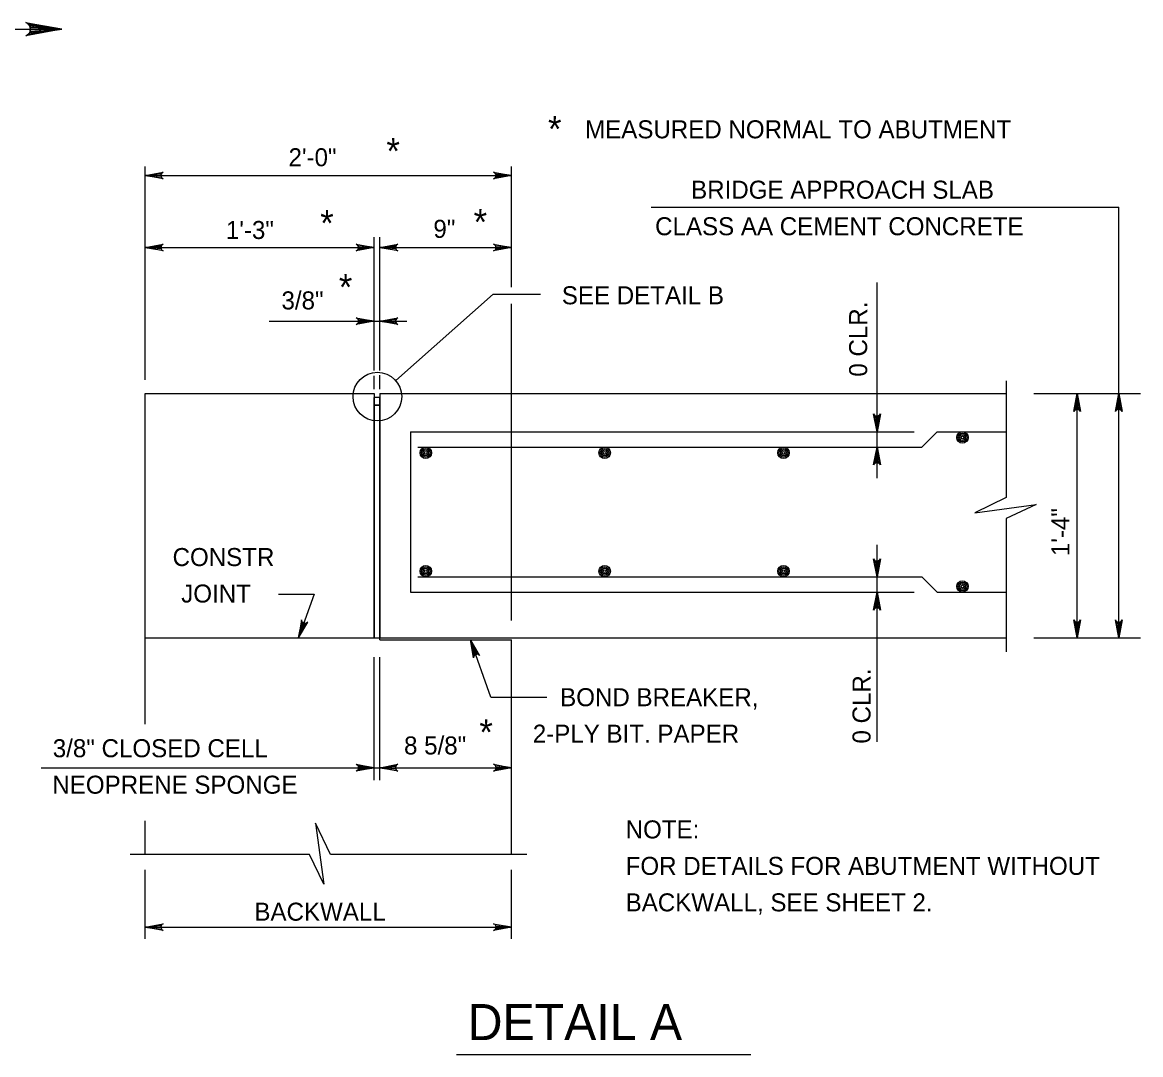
# Model space of a CAD drawing. Extents: x 638079 to 640019, y 297691 to 298879.
# Drawn here: x 638757.3 to 638943.4, y 298459.3 to 298631 of the extents above; entities that cross this region are included whole.
import ezdxf

# ---------------------------------------------------------------- set-up
doc = ezdxf.new("R2010")
doc.units = 0
doc.layers.add('1', color=7, linetype='Continuous')

msp = doc.modelspace()

# ---------------------------------------------------------------- linework, layer by layer
at = {"layer": '1'}
for p, q in [((638683.38, 298629.92), (638763.86, 298629.92)), ((638777.75, 298571.56), (638777.75, 298607.05)), ((638838.71, 298586.96), (638838.71, 298607.05)), ((638777.75, 298605.56), (638838.71, 298605.56)), ((638861.93, 298600.3), (638939.71, 298600.3)), ((638939.71, 298528.61), (638939.71, 298600.3)), ((638815.85, 298573.11), (638815.85, 298595.29)), ((638816.8, 298583.27), (638816.8, 298595.29)), ((638777.75, 298593.55), (638815.85, 298593.55)), ((638816.8, 298593.55), (638838.71, 298593.55)), ((638899.5, 298555.2), (638899.5, 298587.76)), ((638835.66, 298585.8), (638819.42, 298571.45)), ((638835.66, 298585.8), (638843.52, 298585.8)), ((638816.8, 298573.11), (638816.8, 298583.27)), ((638838.71, 298531.48), (638838.71, 298584.18)), ((638798.37, 298581.31), (638821.29, 298581.31)), ((638815.85, 298570.01), (638815.85, 298572.2)), ((638816.8, 298570.01), (638816.8, 298572.32)), ((638920.99, 298571.37), (638920.99, 298551.97)), ((638777.75, 298569.25), (638815.85, 298569.25)), ((638777.75, 298514.24), (638777.75, 298569.25)), ((638815.85, 298569.25), (638815.85, 298528.61)), ((638815.85, 298528.61), (638815.85, 298568.61)), ((638816.8, 298569.25), (638920.99, 298569.25)), ((638816.8, 298569.25), (638816.8, 298528.61)), ((638925.57, 298569.25), (638943.36, 298569.25)), ((638932.79, 298528.61), (638932.79, 298569.25)), ((638815.85, 298567.34), (638816.8, 298567.34)), ((638821.88, 298562.9), (638821.88, 298536.23)), ((638821.88, 298562.9), (638905.7, 298562.9)), ((638906.97, 298560.36), (638909.51, 298562.9)), ((638909.51, 298562.9), (638920.99, 298562.9)), ((638823.1, 298560.36), (638906.97, 298560.36)), ((638920.99, 298548.45), (638920.99, 298526.3)), ((638899.5, 298511.32), (638899.5, 298544.07)), ((638823.1, 298538.77), (638906.97, 298538.77)), ((638906.97, 298538.77), (638909.51, 298536.23)), ((638821.88, 298536.23), (638905.7, 298536.23)), ((638909.51, 298536.23), (638920.99, 298536.23)), ((638799.91, 298535.9), (638805.86, 298535.9)), ((638805.86, 298535.9), (638803.26, 298528.61)), ((638777.75, 298528.61), (638815.85, 298528.61)), ((638815.85, 298528.61), (638920.99, 298528.61)), ((638815.85, 298528.61), (638838.71, 298528.61)), ((638816.8, 298528.3), (638816.8, 298528.61)), ((638816.8, 298528.3), (638838.71, 298528.3)), ((638835.26, 298518.76), (638831.86, 298528.3)), ((638838.71, 298492.58), (638838.71, 298528.3)), ((638925.57, 298528.61), (638943.36, 298528.61)), ((638815.85, 298504.91), (638815.85, 298525.41)), ((638816.8, 298504.91), (638816.8, 298525.41)), ((638835.26, 298518.76), (638844.55, 298518.76)), ((638760.45, 298507.01), (638838.71, 298507.01)), ((638777.75, 298492.58), (638777.75, 298498.18)), ((638805.08, 298492.58), (638775.22, 298492.58)), ((638841.26, 298492.58), (638808.6, 298492.58)), ((638777.75, 298478.53), (638777.75, 298490.03)), ((638838.71, 298478.53), (638838.71, 298490.03)), ((638777.75, 298480.49), (638838.71, 298480.49)), ((638829.54, 298459.26), (638878.48, 298459.26))]:
    msp.add_line(p, q, dxfattribs=at)
for points in [[(638763.86, 298629.92), (638757.89, 298628.8), (638758.12, 298628.96), (638758.35, 298629.12), (638758.47, 298629.32), (638758.59, 298629.52), (638758.63, 298629.72), (638758.66, 298629.92), (638758.63, 298630.12), (638758.59, 298630.32), (638758.47, 298630.52), (638758.35, 298630.72), (638758.12, 298630.88), (638757.89, 298631.04), (638763.86, 298629.92), (638758.12, 298630.88), (638758.35, 298630.72), (638763.86, 298629.92), (638758.47, 298630.52), (638758.59, 298630.32), (638763.86, 298629.92), (638758.63, 298630.12), (638758.66, 298629.92), (638763.86, 298629.92), (638758.63, 298629.72), (638758.59, 298629.52), (638763.86, 298629.92), (638758.47, 298629.32), (638758.35, 298629.12), (638763.86, 298629.92), (638758.12, 298628.96)], [(638777.75, 298605.56), (638780.73, 298606.12), (638780.5, 298605.96), (638780.38, 298605.76), (638780.35, 298605.56), (638780.38, 298605.36), (638780.5, 298605.16), (638780.73, 298605), (638777.75, 298605.56), (638780.5, 298605.16), (638780.38, 298605.36), (638777.75, 298605.56), (638780.35, 298605.56), (638780.38, 298605.76), (638777.75, 298605.56), (638780.5, 298605.96)], [(638838.71, 298605.56), (638835.72, 298605), (638835.95, 298605.16), (638836.07, 298605.36), (638836.11, 298605.56), (638836.07, 298605.76), (638835.95, 298605.96), (638835.72, 298606.12), (638838.71, 298605.56), (638835.95, 298605.96), (638836.07, 298605.76), (638838.71, 298605.56), (638836.11, 298605.56), (638836.07, 298605.36), (638838.71, 298605.56), (638835.95, 298605.16)], [(638777.75, 298593.55), (638780.73, 298594.11), (638780.5, 298593.95), (638780.38, 298593.75), (638780.35, 298593.55), (638780.38, 298593.35), (638780.5, 298593.15), (638780.73, 298592.99), (638777.75, 298593.55), (638780.5, 298593.15), (638780.38, 298593.35), (638777.75, 298593.55), (638780.35, 298593.55), (638780.38, 298593.75), (638777.75, 298593.55), (638780.5, 298593.95)], [(638815.85, 298593.55), (638812.86, 298592.99), (638813.09, 298593.15), (638813.21, 298593.35), (638813.25, 298593.55), (638813.21, 298593.75), (638813.09, 298593.95), (638812.86, 298594.11), (638815.85, 298593.55), (638813.09, 298593.95), (638813.21, 298593.75), (638815.85, 298593.55), (638813.25, 298593.55), (638813.21, 298593.35), (638815.85, 298593.55), (638813.09, 298593.15)], [(638816.8, 298593.55), (638819.78, 298594.11), (638819.55, 298593.95), (638819.43, 298593.75), (638819.4, 298593.55), (638819.43, 298593.35), (638819.55, 298593.15), (638819.78, 298592.99), (638816.8, 298593.55), (638819.55, 298593.15), (638819.43, 298593.35), (638816.8, 298593.55), (638819.4, 298593.55), (638819.43, 298593.75), (638816.8, 298593.55), (638819.55, 298593.95)], [(638838.71, 298593.55), (638835.72, 298592.99), (638835.95, 298593.15), (638836.07, 298593.35), (638836.11, 298593.55), (638836.07, 298593.75), (638835.95, 298593.95), (638835.72, 298594.11), (638838.71, 298593.55), (638835.95, 298593.95), (638836.07, 298593.75), (638838.71, 298593.55), (638836.11, 298593.55), (638836.07, 298593.35), (638838.71, 298593.55), (638835.95, 298593.15)], [(638815.85, 298581.31), (638812.86, 298580.75), (638813.09, 298580.91), (638813.21, 298581.11), (638813.25, 298581.31), (638813.21, 298581.51), (638813.09, 298581.71), (638812.86, 298581.87), (638815.85, 298581.31), (638813.09, 298581.71), (638813.21, 298581.51), (638815.85, 298581.31), (638813.25, 298581.31), (638813.21, 298581.11), (638815.85, 298581.31), (638813.09, 298580.91)], [(638816.8, 298581.31), (638819.78, 298581.87), (638819.55, 298581.71), (638819.43, 298581.51), (638819.4, 298581.31), (638819.43, 298581.11), (638819.55, 298580.91), (638819.78, 298580.75), (638816.8, 298581.31), (638819.55, 298580.91), (638819.43, 298581.11), (638816.8, 298581.31), (638819.4, 298581.31), (638819.43, 298581.51), (638816.8, 298581.31), (638819.55, 298581.71)], [(638932.79, 298569.25), (638933.34, 298566.27), (638933.19, 298566.5), (638932.99, 298566.61), (638932.79, 298566.65), (638932.59, 298566.61), (638932.39, 298566.5), (638932.23, 298566.27), (638932.79, 298569.25), (638932.39, 298566.5), (638932.59, 298566.61), (638932.79, 298569.25), (638932.79, 298566.65), (638932.99, 298566.61), (638932.79, 298569.25), (638933.19, 298566.5)], [(638939.71, 298569.25), (638940.27, 298566.27), (638940.11, 298566.5), (638939.91, 298566.61), (638939.71, 298566.65), (638939.51, 298566.61), (638939.31, 298566.5), (638939.15, 298566.27), (638939.71, 298569.25), (638939.31, 298566.5), (638939.51, 298566.61), (638939.71, 298569.25), (638939.71, 298566.65), (638939.91, 298566.61), (638939.71, 298569.25), (638940.11, 298566.5)], [(638899.5, 298562.9), (638898.94, 298565.88), (638899.1, 298565.65), (638899.3, 298565.53), (638899.5, 298565.5), (638899.7, 298565.53), (638899.9, 298565.65), (638900.06, 298565.88), (638899.5, 298562.9), (638899.9, 298565.65), (638899.7, 298565.53), (638899.5, 298562.9), (638899.5, 298565.5), (638899.3, 298565.53), (638899.5, 298562.9), (638899.1, 298565.65)], [(638899.5, 298560.36), (638900.06, 298557.38), (638899.9, 298557.61), (638899.7, 298557.73), (638899.5, 298557.76), (638899.3, 298557.73), (638899.1, 298557.61), (638898.94, 298557.38), (638899.5, 298560.36), (638899.1, 298557.61), (638899.3, 298557.73), (638899.5, 298560.36), (638899.5, 298557.76), (638899.7, 298557.73), (638899.5, 298560.36), (638899.9, 298557.61)], [(638920.99, 298551.97), (638915.8, 298549.43), (638925.95, 298550.81), (638920.99, 298548.45)], [(638899.5, 298538.77), (638898.94, 298541.75), (638899.1, 298541.52), (638899.3, 298541.4), (638899.5, 298541.37), (638899.7, 298541.4), (638899.9, 298541.52), (638900.06, 298541.75), (638899.5, 298538.77), (638899.9, 298541.52), (638899.7, 298541.4), (638899.5, 298538.77), (638899.5, 298541.37), (638899.3, 298541.4), (638899.5, 298538.77), (638899.1, 298541.52)], [(638899.5, 298536.23), (638900.06, 298533.25), (638899.9, 298533.48), (638899.7, 298533.6), (638899.5, 298533.63), (638899.3, 298533.6), (638899.1, 298533.48), (638898.94, 298533.25), (638899.5, 298536.23), (638899.1, 298533.48), (638899.3, 298533.6), (638899.5, 298536.23), (638899.5, 298533.63), (638899.7, 298533.6), (638899.5, 298536.23), (638899.9, 298533.48)], [(638803.26, 298528.61), (638804.79, 298531.23), (638804.56, 298531.07), (638804.33, 298531.02), (638804.13, 298531.06), (638803.95, 298531.16), (638803.81, 298531.34), (638803.73, 298531.61), (638803.26, 298528.61), (638803.81, 298531.34), (638803.95, 298531.16), (638803.26, 298528.61), (638804.13, 298531.06), (638804.33, 298531.02), (638803.26, 298528.61), (638804.56, 298531.07)], [(638932.79, 298528.61), (638932.23, 298531.59), (638932.39, 298531.36), (638932.59, 298531.24), (638932.79, 298531.21), (638932.99, 298531.24), (638933.19, 298531.36), (638933.34, 298531.59), (638932.79, 298528.61), (638933.19, 298531.36), (638932.99, 298531.24), (638932.79, 298528.61), (638932.79, 298531.21), (638932.59, 298531.24), (638932.79, 298528.61), (638932.39, 298531.36)], [(638939.71, 298528.61), (638939.15, 298531.59), (638939.31, 298531.36), (638939.51, 298531.24), (638939.71, 298531.21), (638939.91, 298531.24), (638940.11, 298531.36), (638940.27, 298531.59), (638939.71, 298528.61), (638940.11, 298531.36), (638939.91, 298531.24), (638939.71, 298528.61), (638939.71, 298531.21), (638939.51, 298531.24), (638939.71, 298528.61), (638939.31, 298531.36)], [(638831.86, 298528.3), (638833.39, 298525.68), (638833.16, 298525.85), (638832.94, 298525.89), (638832.74, 298525.86), (638832.56, 298525.76), (638832.41, 298525.58), (638832.34, 298525.31), (638831.86, 298528.3), (638832.41, 298525.58), (638832.56, 298525.76), (638831.86, 298528.3), (638832.74, 298525.86), (638832.94, 298525.89), (638831.86, 298528.3), (638833.16, 298525.85)], [(638815.85, 298507.01), (638812.86, 298506.45), (638812.98, 298506.53), (638813.09, 298506.61), (638813.15, 298506.71), (638813.21, 298506.81), (638813.23, 298506.91), (638813.25, 298507.01), (638813.23, 298507.11), (638813.21, 298507.21), (638813.15, 298507.31), (638813.09, 298507.41), (638812.98, 298507.49), (638812.86, 298507.57), (638815.85, 298507.01), (638812.98, 298507.49), (638813.09, 298507.41), (638815.85, 298507.01), (638813.15, 298507.31), (638813.21, 298507.21), (638815.85, 298507.01), (638813.23, 298507.11), (638813.25, 298507.01), (638815.85, 298507.01), (638813.23, 298506.91), (638813.21, 298506.81), (638815.85, 298507.01), (638813.15, 298506.71), (638813.09, 298506.61), (638815.85, 298507.01), (638812.98, 298506.53)], [(638816.8, 298507.01), (638819.78, 298507.57), (638819.55, 298507.41), (638819.43, 298507.21), (638819.4, 298507.01), (638819.43, 298506.81), (638819.55, 298506.61), (638819.78, 298506.45), (638816.8, 298507.01), (638819.55, 298506.61), (638819.43, 298506.81), (638816.8, 298507.01), (638819.4, 298507.01), (638819.43, 298507.21), (638816.8, 298507.01), (638819.55, 298507.41)], [(638838.71, 298507.01), (638835.72, 298506.45), (638835.95, 298506.61), (638836.07, 298506.81), (638836.11, 298507.01), (638836.07, 298507.21), (638835.95, 298507.41), (638835.72, 298507.57), (638838.71, 298507.01), (638835.95, 298507.41), (638836.07, 298507.21), (638838.71, 298507.01), (638836.11, 298507.01), (638836.07, 298506.81), (638838.71, 298507.01), (638835.95, 298506.61)], [(638808.6, 298492.58), (638806.06, 298497.77), (638807.44, 298487.62), (638805.08, 298492.58)], [(638777.75, 298480.49), (638780.73, 298481.05), (638780.5, 298480.89), (638780.38, 298480.69), (638780.35, 298480.49), (638780.38, 298480.29), (638780.5, 298480.09), (638780.73, 298479.93), (638777.75, 298480.49), (638780.5, 298480.09), (638780.38, 298480.29), (638777.75, 298480.49), (638780.35, 298480.49), (638780.38, 298480.69), (638777.75, 298480.49), (638780.5, 298480.89)], [(638838.71, 298480.49), (638835.72, 298479.93), (638835.95, 298480.09), (638836.07, 298480.29), (638836.11, 298480.49), (638836.07, 298480.69), (638835.95, 298480.89), (638835.72, 298481.05), (638838.71, 298480.49), (638835.95, 298480.89), (638836.07, 298480.69), (638838.71, 298480.49), (638836.11, 298480.49), (638836.07, 298480.29), (638838.71, 298480.49), (638835.95, 298480.09)]]:
    msp.add_lwpolyline(points, dxfattribs=at)
for points in [[(638815.85, 298567.34), (638816.8, 298567.34), (638816.8, 298568.61), (638815.85, 298568.61)], [(638815.85, 298528.61), (638816.8, 298528.61), (638816.8, 298567.34), (638815.85, 298567.34)]]:
    msp.add_lwpolyline(points, close=True, dxfattribs=at)
for centre, radius in [((638816.38, 298568.76), 4.05), ((638913.71, 298561.95), 0.952), ((638913.71, 298561.95), 0.714), ((638913.71, 298561.95), 0.476), ((638913.71, 298561.95), 0.238), ((638824.42, 298559.41), 0.952), ((638854.18, 298559.41), 0.952), ((638883.95, 298559.41), 0.952), ((638824.42, 298559.41), 0.714), ((638824.42, 298559.41), 0.476), ((638824.42, 298559.41), 0.238), ((638854.18, 298559.41), 0.714), ((638854.18, 298559.41), 0.476), ((638854.18, 298559.41), 0.238), ((638883.95, 298559.41), 0.714), ((638883.95, 298559.41), 0.476), ((638883.95, 298559.41), 0.238), ((638824.42, 298539.72), 0.952), ((638824.42, 298539.72), 0.714), ((638824.42, 298539.72), 0.476), ((638824.42, 298539.72), 0.238), ((638854.18, 298539.72), 0.952), ((638854.18, 298539.72), 0.714), ((638854.18, 298539.72), 0.476), ((638854.18, 298539.72), 0.238), ((638883.95, 298539.72), 0.952), ((638883.95, 298539.72), 0.714), ((638883.95, 298539.72), 0.476), ((638883.95, 298539.72), 0.238), ((638913.71, 298537.18), 0.952), ((638913.71, 298537.18), 0.714), ((638913.71, 298537.18), 0.476), ((638913.71, 298537.18), 0.238)]:
    msp.add_circle(centre, radius, dxfattribs=at)

# ---------------------------------------------------------------- texts
for s, height, p in [('*', 4.32, (638844.76, 298611.14)), ('MEASURED NORMAL TO ABUTMENT', 3, (638850.93, 298611.74)), ('*', 4.32, (638817.88, 298607.46)), ('2\'-0"', 3, (638801.59, 298607.09)), ('BRIDGE APPROACH SLAB', 3, (638868.57, 298601.69)), ('*', 4.32, (638806.86, 298595.47)), ('*', 4.32, (638832.38, 298595.66)), ('1\'-3"', 3, (638791.17, 298594.99)), ('9"', 3, (638825.69, 298595.18)), ('CLASS AA CEMENT CONCRETE', 3, (638862.58, 298595.61)), ('*', 4.32, (638809.96, 298584.83)), ('3/8"', 3, (638800.42, 298583.27)), ('SEE DETAIL B', 3, (638847.06, 298584.12)), ('CONSTR', 3, (638782.3, 298540.56)), ('JOINT', 3, (638783.74, 298534.49)), ('BOND BREAKER,', 3, (638846.78, 298517.24)), ('*', 4.32, (638833.34, 298510.76)), ('2-PLY BIT. PAPER', 3, (638842.23, 298511.17)), ('8 5/8"', 3, (638820.81, 298509.21)), ('3/8" CLOSED CELL', 3, (638762.37, 298508.75)), ('NEOPRENE SPONGE', 3, (638762.3, 298502.68)), ('NOTE:', 3, (638857.68, 298495.24)), ('FOR DETAILS FOR ABUTMENT WITHOUT', 3, (638857.68, 298489.17)), ('BACKWALL, SEE SHEET 2.', 3, (638857.68, 298483.1)), ('BACKWALL', 3, (638795.91, 298481.55)), ('DETAIL A', 6, (638831.4, 298461.68))]:
    msp.add_text(s, height=height, dxfattribs=at).set_placement(p)
for s, p in [('0 CLR.', (638897.86, 298572.08)), ('1\'-4"', (638931.52, 298542.22)), ('0 CLR.', (638898.42, 298511.03))]:
    msp.add_text(s, height=3, rotation=90, dxfattribs=at).set_placement(p)

doc.saveas('drawing.dxf')
